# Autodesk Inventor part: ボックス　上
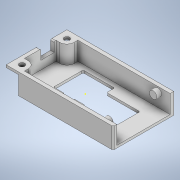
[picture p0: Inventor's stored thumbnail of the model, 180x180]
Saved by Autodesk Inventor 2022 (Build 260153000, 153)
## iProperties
Created: 2024-12
Part Number: ボックス　上
Material: 一般
Document SubType Name: Modeling
Designer: jsat7
Density: 1 g/cm^3
Appearance: 既定
Author: jsat7
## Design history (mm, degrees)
sketch "スケッチ1"
  geometry: L1 (19.188, -11.63)-(-24.812, -11.63); L2 (-24.812, -11.63)-(-24.812, 13.37); L3 (-24.812, 13.37)-(19.188, 13.37); L4 (19.188, 13.37)-(19.188, -11.63); 1 further point
  constraints: 8 end point, 2 parallel, 1 horizontal, 1 perpendicular
  dimensions: "d0" = 44 distance of L1.start L1.end; "d1" = 25 distance of L3.end L1.start
extrude "押し出し1" new body sketch "スケッチ1" distance "d2" = 1; taper "d3" = 0 deg
sketch "スケッチ2"
  geometry: L1 (-13.188, 10.13)-(24.812, 10.13); L2 (24.812, -11.87)-(-13.188, -11.87); L3 (-13.188, -11.87)-(-13.188, 10.13); L4 (24.812, 11.63)-(-19.188, 11.63) reference; L5 (-19.188, -13.37)-(24.812, -13.37) reference; L6 (-19.188, 11.63)-(-19.188, -13.37) reference; L7 (24.812, -13.37)-(24.812, 11.63) reference; 3 further points
  constraints: 6 end point, 1 horizontal, 1 parallel
  dimensions: "d4" = 1.5 distance between parallel lines of L1 L4; "d5" = 1.5 distance between parallel lines of L5 L2; "d6" = 6 distance between parallel lines of L6 L3
extrude "押し出し2" join sketch "スケッチ2" distance "d8" = 7.5; taper "d9" = 0 deg
sketch "スケッチ3"
  geometry: L1 (-13.188, -11.87)-(-13.188, 10.13) reference; L2 (-13.188, 5.63)-(-17.688, 5.63); L3 (-17.688, 5.63)-(-17.688, -7.37); L4 (-17.688, -7.37)-(-13.188, -7.37); L5 (-13.188, -7.37)-(-13.188, 5.63); L6 (24.812, 11.63)-(-19.188, 11.63) reference; L7 (-19.188, -13.37)-(24.812, -13.37) reference; L8 (-19.188, 11.63)-(-19.188, -13.37) reference; 2 further points
  constraints: 8 end point, 2 parallel, 1 horizontal, 1 perpendicular, 1 point on line
  dimensions: "d10" = 6 distance between parallel lines of L6 L2; "d11" = 6 distance between parallel lines of L7 L4; "d12" = 1.5 distance between parallel lines of L8 L3
extrude "押し出し3" cut sketch "スケッチ3" distance "d13" = 7.5; taper "d14" = 0 deg
fillet "フィレット1" dims "d15" = 3
fillet "フィレット2" dims "d16" = 3
sketch "スケッチ4"
  geometry: L1 (-19.188, -11.63)-(-19.188, 13.37) reference; L2 (-19.188, -11.63)-(-14.188, -11.63); L3 (-14.188, -11.63)-(-14.188, -6.63); L4 (-14.188, -6.63)-(-19.188, -6.63); L5 (-19.188, -6.63)-(-19.188, -11.63); L6 (-19.188, 13.37)-(-14.188, 13.37); L7 (-14.188, 13.37)-(-14.188, 8.37); L8 (-14.188, 8.37)-(-19.188, 8.37); L9 (-19.188, 8.37)-(-19.188, 13.37); 3 further points
  constraints: 16 end point, 4 parallel, 2 horizontal, 2 perpendicular
  dimensions: "d17" = 5 distance of L7.end L8.end; "d18" = 5 distance of L6.end L7.end; "d19" = 5 distance of L3.end L4.end; "d20" = 5 distance of L2.end L3.end
extrude "押し出し4" cut sketch "スケッチ4" distance "d21" = 7.5; taper "d22" = 0 deg
fillet "フィレット3" dims "d23" = 2
fillet "フィレット4" dims "d24" = 2
sketch "スケッチ5"
  geometry: L1 (38, 0)-(38, 7.5) reference; L2 (0, 7.5)-(38, 7.5) reference; C1 r 1.5 at (33, 5.5); 1 further point
  constraints: 1 centre point
  dimensions: "d25" = 5 distance from line of L1 C1.centre; "d26" = 2 distance from line of L2 C1.centre; "d27" = 3 diameter of C1
extrude "押し出し5" join sketch "スケッチ5" distance "d28" = 2; taper "d29" = 0 deg
sketch "スケッチ6"
  geometry: L1 (0, 0)-(0, 7.5) reference; L2 (0, 7.5)-(38, 7.5) reference; C1 r 1.5 at (5, 5.5); 1 further point
  constraints: 1 centre point
  dimensions: "d30" = 5 distance from line of L1 C1.centre; "d31" = 2 distance from line of L2 C1.centre; "d32" = 3 diameter of C1
extrude "押し出し6" join sketch "スケッチ6" distance "d33" = 2; taper "d34" = 0 deg
sketch "スケッチ7"
  geometry: L1 (24.812, 11.63)-(-19.188, 11.63) reference; L2 (-19.188, 11.63)-(-19.188, -13.37) reference; L3 (-19.188, -13.37)-(24.812, -13.37) reference; C1 r 1.1 at (-15.938, -10.12); C2 r 1.1 at (-15.938, 8.38); 1 further point
  constraints: 2 centre point
  dimensions: "d35" = 3.25 distance from line of L1 C2.centre; "d36" = 3.25 distance from line of L2 C2.centre; "d37" = 3.25 distance from line of L2 C1.centre; "d38" = 3.25 distance from line of L3 C1.centre; "d39" = 2.2 diameter of C1; "d40" = 2.2 diameter of C2
extrude "押し出し7" cut sketch "スケッチ7" distance "d41" = 12; taper "d42" = 0 deg
sketch "スケッチ8"
  geometry: 1 further point
sketch "スケッチ10"
  geometry: L1 (19, 0)-(6, 0) reference; L2 (6.7, 0)-(12.2, 0); L3 (12.2, 0)-(12.2, -4); L4 (12.2, -4)-(6.7, -4); L5 (6.7, -4)-(6.7, 0); L6 (0, -8.5)-(0, -1) reference; 2 further points
  constraints: 8 end point, 2 parallel, 1 horizontal, 1 perpendicular, 1 point on line
  dimensions: "d43" = 6.7 distance between parallel lines of L5 L6; "d44" = 5.5 distance between parallel lines of L3 L5; "d45" = 4 distance between parallel lines of L1 L4
extrude "押し出し8" cut sketch "スケッチ10" distance "d46" = 1.5; taper "d47" = 0 deg
fillet "フィレット5" dims "d48" = 0.5
fillet "フィレット6" dims "d49" = 0.5
sketch "スケッチ11"
  geometry: L1 (3.912, 6.77)-(17.612, 6.77); L2 (17.612, 6.77)-(17.612, -4.93); L3 (17.612, -4.93)-(3.912, -4.93); L4 (3.912, -4.93)-(3.912, 6.77); L5 (24.812, 13.37)-(24.812, -11.63) reference; L6 (-14.188, 13.37)-(24.812, 13.37) reference; L7 (3.912, 4.07)-(-8.988, 4.07); L8 (-8.988, 4.07)-(-8.988, -8.13); L9 (-8.988, -8.13)-(3.912, -8.13); L10 (3.912, -8.13)-(3.912, 4.07); L11 (-19.188, -6.63)-(-19.188, 8.37) reference; L12 (24.812, -11.63)-(-14.188, -11.63) reference; A1 r 2.25 centre (-2.538, 4.07) between (-0.288, 4.07) and (-4.788, 4.07); A2 r 2.25 centre (9.166, 6.77) between (11.416, 6.77) and (6.916, 6.77); 2 further points
  constraints: 16 end point, 6 point on line, 4 parallel, 4 point on circle, 2 centre point, 2 horizontal, 2 perpendicular, 1 midpoint
  dimensions: "d50" = 7.2 distance between parallel lines of L5 L2; "d51" = 6.6 distance between parallel lines of L6 L1; "d52" = 13.7 distance of L1.start L1.end; "d53" = 11.7 distance of L1.end L2.end; "d54" = 9.3 distance between parallel lines of L6 L7; "d55" = 10.2 distance between parallel lines of L11 L8; "d56" = 3.5 distance between parallel lines of L12 L9; "d57" = 4.5 diameter of A1; "d58" = 4.5 diameter of A2
extrude "押し出し9" cut sketch "スケッチ11" distance "d59" = 1.5; taper "d60" = 0 deg
fillet "フィレット7" dims "d61" = 0.5
chamfer "面取り1" distance "d62" = 0.5; stored, may be unused: second distance "d63" = 2, angle "d64" = 45 deg
node "ソリッド1"
